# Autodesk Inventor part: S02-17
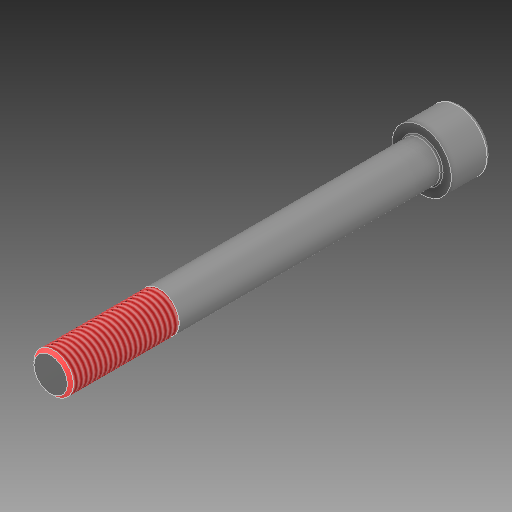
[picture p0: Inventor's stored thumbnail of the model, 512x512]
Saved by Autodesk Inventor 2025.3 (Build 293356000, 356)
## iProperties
Manager: ISO 4762 (DIN 912)
Created: 2025-04
Part Number: S02-17
Material: Všeobecné
Document SubType Name: Modeling
Designer: Patrik
Density: 1 g/cm^3
Appearance: Výchozí
Stock Number: E 1200/16x150
Description: Imbusový šroub s válcovou hlavou
User Status: 12.9
Author: Patrik
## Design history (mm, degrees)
feature "Base1"
feature "Závit1" dims "d0" = 42.775, "d1" = 0
node "Těleso1"
